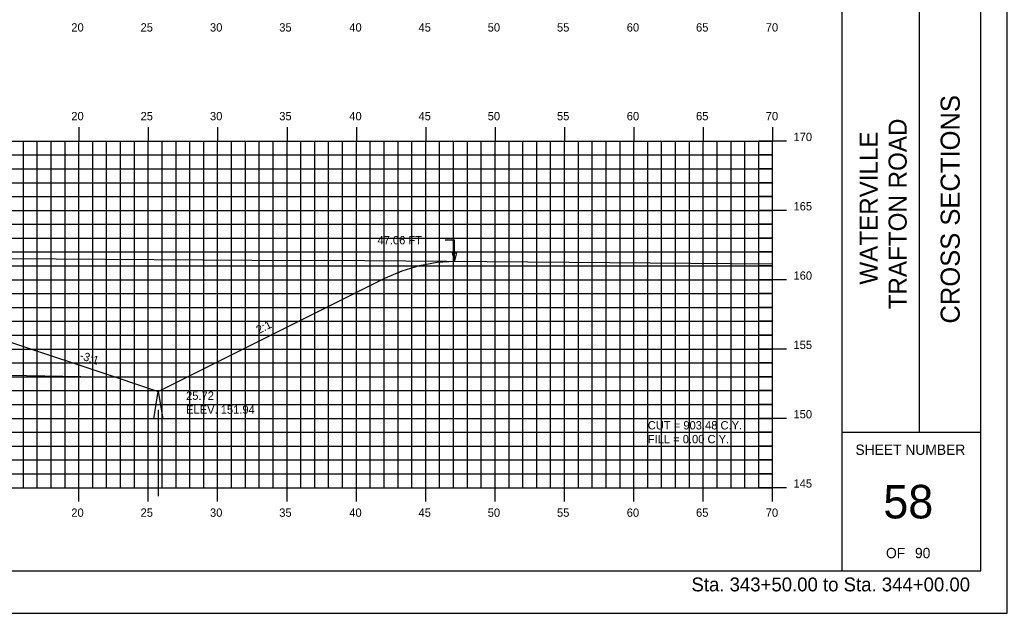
# Model space of a CAD drawing. Extents: x 1143420 to 1143590, y 608981 to 609091.
# Drawn here: x 1143518.8 to 1143590, y 608981.3 to 609024.1 of the extents above; entities that cross this region are included whole.
import ezdxf

# ---------------------------------------------------------------- set-up
doc = ezdxf.new("R2010")
doc.units = 0
for name, color, linetype in [('ANNOTATION', 7, 'Continuous'), ('BORDER', 7, 'Continuous'), ('D_Drainage_Ditch_Line', 7, 'Continuous'), ('D_Roadway_SlopeLines', 7, 'Continuous'), ('D_Roadway_SubGrade', 7, 'Continuous'), ('D_Text_Standard', 7, 'Continuous'), ('H_V ANNOTATION', 7, 'Continuous'), ('HIGHWAY_TITLE', 7, 'Continuous'), ('MAJOR', 7, 'Continuous'), ('MINOR', 7, 'Continuous'), ('PLOT BOUNDARY', 7, 'Continuous'), ('S_Roadway_Centerline', 7, 'Continuous')]:
    doc.layers.add(name, color=color, linetype=linetype)

msp = doc.modelspace()

# ---------------------------------------------------------------- linework, layer by layer
msp.add_lwpolyline([(1143457.318, 609006.487), (1143458.568, 609006.213), (1143459.818, 609005.839), (1143461.068, 609005.365), (1143462.318, 609004.79), (1143477.355, 608997.271), (1143480.355, 608998.271), (1143488.079, 609000.846), (1143488.08, 609000.846), (1143492.08, 609001.006), (1143503.08, 609001.226), (1143514.08, 609001.006), (1143518.08, 609000.846), (1143525.803, 608998.271), (1143528.803, 608997.271), (1143545.139, 609005.439), (1143546.389, 609005.985), (1143547.639, 609006.372), (1143548.889, 609006.599), (1143550.139, 609006.669)])
at = {"layer": 'BORDER'}
for p, q in [((1143578.08, 608984.335), (1143578.08, 609089.335)), ((1143583.671, 608994.338), (1143583.671, 609029.338)), ((1143578.08, 608994.338), (1143588.08, 608994.338))]:
    msp.add_line(p, q, dxfattribs=at)
msp.add_lwpolyline([(1143428.08, 608984.335), (1143588.08, 608984.335), (1143588.08, 609089.335), (1143428.08, 609089.335)], close=True, dxfattribs=at)
at = {"layer": 'D_Drainage_Ditch_Line'}
msp.add_line((1143528.803, 608995.959), (1143528.803, 608989.716), dxfattribs=at)
msp.add_lwpolyline([(1143529.131, 608995.303), (1143528.475, 608995.303), (1143528.803, 608997.271)], close=True, dxfattribs=at)
at = {"layer": 'D_Roadway_SlopeLines'}
for points in [[(1143528.803, 608997.271), (1143545.139, 609005.439), (1143546.389, 609005.985), (1143547.639, 609006.372), (1143548.889, 609006.599), (1143550.139, 609006.669)], [(1143525.803, 608998.271), (1143528.803, 608997.271)]]:
    msp.add_lwpolyline(points, dxfattribs=at)
at = {"layer": 'D_Roadway_SubGrade'}
msp.add_lwpolyline([(1143514.08, 609000.589), (1143514.08, 609000.756), (1143518.08, 609000.596), (1143518.08, 609000.846), (1143518.08, 609000.846), (1143525.803, 608998.271), (1143514.08, 608998.506)], close=True, dxfattribs=at)
at = {"layer": 'D_Text_Standard'}
msp.add_lwpolyline([(1143550.139, 609006.689), (1143550.146, 609008.19), (1143549.466, 609008.19)], dxfattribs=at)
msp.add_lwpolyline([(1143550.139, 609006.689), (1143549.996, 609007.272), (1143550.287, 609007.271)], close=True, dxfattribs=at)
at = {"layer": 'MAJOR'}
for p, q in [((1143523.08, 609016.337), (1143523.08, 609015.335)), ((1143528.08, 609016.337), (1143528.08, 609015.335)), ((1143533.08, 609016.337), (1143533.08, 609015.335)), ((1143538.08, 609016.337), (1143538.08, 609015.335)), ((1143543.08, 609016.337), (1143543.08, 609015.335)), ((1143548.08, 609016.337), (1143548.08, 609015.335)), ((1143553.08, 609016.337), (1143553.08, 609015.335)), ((1143558.08, 609016.337), (1143558.08, 609015.335)), ((1143563.08, 609016.337), (1143563.08, 609015.335)), ((1143568.08, 609016.337), (1143568.08, 609015.335)), ((1143573.08, 609016.337), (1143573.08, 609015.335)), ((1143433.08, 609015.335), (1143573.08, 609015.335)), ((1143433.08, 609015.335), (1143573.08, 609015.335)), ((1143523.08, 608990.335), (1143523.08, 609015.335)), ((1143528.08, 608990.335), (1143528.08, 609015.335)), ((1143533.08, 608990.335), (1143533.08, 609015.335)), ((1143538.08, 608990.335), (1143538.08, 609015.335)), ((1143543.08, 608990.335), (1143543.08, 609015.335)), ((1143548.08, 608990.335), (1143548.08, 609015.335)), ((1143553.08, 608990.335), (1143553.08, 609015.335)), ((1143558.08, 608990.335), (1143558.08, 609015.335)), ((1143563.08, 608990.335), (1143563.08, 609015.335)), ((1143568.08, 608990.335), (1143568.08, 609015.335)), ((1143574.082, 609015.335), (1143572.078, 609015.335)), ((1143573.08, 608990.335), (1143573.08, 609015.335)), ((1143573.08, 608990.335), (1143573.08, 609015.335)), ((1143433.08, 609010.335), (1143573.08, 609010.335)), ((1143574.082, 609010.335), (1143572.078, 609010.335)), ((1143433.08, 609005.335), (1143573.08, 609005.335)), ((1143574.082, 609005.335), (1143572.078, 609005.335)), ((1143433.08, 609000.335), (1143573.08, 609000.335)), ((1143574.082, 609000.335), (1143572.078, 609000.335)), ((1143433.08, 608995.335), (1143573.08, 608995.335)), ((1143574.082, 608995.335), (1143572.078, 608995.335)), ((1143433.08, 608990.335), (1143573.08, 608990.335)), ((1143433.08, 608990.335), (1143573.08, 608990.335)), ((1143523.08, 608989.333), (1143523.08, 608990.335)), ((1143528.08, 608989.333), (1143528.08, 608990.335)), ((1143533.08, 608989.333), (1143533.08, 608990.335)), ((1143538.08, 608989.333), (1143538.08, 608990.335)), ((1143543.08, 608989.333), (1143543.08, 608990.335)), ((1143548.08, 608989.333), (1143548.08, 608990.335)), ((1143553.08, 608989.333), (1143553.08, 608990.335)), ((1143558.08, 608989.333), (1143558.08, 608990.335)), ((1143563.08, 608989.333), (1143563.08, 608990.335)), ((1143568.08, 608989.333), (1143568.08, 608990.335)), ((1143574.082, 608990.335), (1143572.078, 608990.335)), ((1143573.08, 608989.333), (1143573.08, 608990.335))]:
    msp.add_line(p, q, dxfattribs=at)
at = {"layer": 'MINOR'}
for p, q in [((1143519.08, 608990.335), (1143519.08, 609015.335)), ((1143520.08, 608990.335), (1143520.08, 609015.335)), ((1143521.08, 608990.335), (1143521.08, 609015.335)), ((1143522.08, 608990.335), (1143522.08, 609015.335)), ((1143524.08, 608990.335), (1143524.08, 609015.335)), ((1143525.08, 608990.335), (1143525.08, 609015.335)), ((1143526.08, 608990.335), (1143526.08, 609015.335)), ((1143527.08, 608990.335), (1143527.08, 609015.335)), ((1143529.08, 608990.335), (1143529.08, 609015.335)), ((1143530.08, 608990.335), (1143530.08, 609015.335)), ((1143531.08, 608990.335), (1143531.08, 609015.335)), ((1143532.08, 608990.335), (1143532.08, 609015.335)), ((1143534.08, 608990.335), (1143534.08, 609015.335)), ((1143535.08, 608990.335), (1143535.08, 609015.335)), ((1143536.08, 608990.335), (1143536.08, 609015.335)), ((1143537.08, 608990.335), (1143537.08, 609015.335)), ((1143539.08, 608990.335), (1143539.08, 609015.335)), ((1143540.08, 608990.335), (1143540.08, 609015.335)), ((1143541.08, 608990.335), (1143541.08, 609015.335)), ((1143542.08, 608990.335), (1143542.08, 609015.335)), ((1143544.08, 608990.335), (1143544.08, 609015.335)), ((1143545.08, 608990.335), (1143545.08, 609015.335)), ((1143546.08, 608990.335), (1143546.08, 609015.335)), ((1143547.08, 608990.335), (1143547.08, 609015.335)), ((1143549.08, 608990.335), (1143549.08, 609015.335)), ((1143550.08, 608990.335), (1143550.08, 609015.335)), ((1143551.08, 608990.335), (1143551.08, 609015.335)), ((1143552.08, 608990.335), (1143552.08, 609015.335)), ((1143554.08, 608990.335), (1143554.08, 609015.335)), ((1143555.08, 608990.335), (1143555.08, 609015.335)), ((1143556.08, 608990.335), (1143556.08, 609015.335)), ((1143557.08, 608990.335), (1143557.08, 609015.335)), ((1143559.08, 608990.335), (1143559.08, 609015.335)), ((1143560.08, 608990.335), (1143560.08, 609015.335)), ((1143561.08, 608990.335), (1143561.08, 609015.335)), ((1143562.08, 608990.335), (1143562.08, 609015.335)), ((1143564.08, 608990.335), (1143564.08, 609015.335)), ((1143565.08, 608990.335), (1143565.08, 609015.335)), ((1143566.08, 608990.335), (1143566.08, 609015.335)), ((1143567.08, 608990.335), (1143567.08, 609015.335)), ((1143569.08, 608990.335), (1143569.08, 609015.335)), ((1143570.08, 608990.335), (1143570.08, 609015.335)), ((1143571.08, 608990.335), (1143571.08, 609015.335)), ((1143572.08, 608990.335), (1143572.08, 609015.335)), ((1143433.08, 609014.335), (1143573.08, 609014.335)), ((1143573.08, 609014.335), (1143572.078, 609014.335)), ((1143433.08, 609013.335), (1143573.08, 609013.335)), ((1143573.08, 609013.335), (1143572.078, 609013.335)), ((1143433.08, 609012.335), (1143573.08, 609012.335)), ((1143573.08, 609012.335), (1143572.078, 609012.335)), ((1143433.08, 609011.335), (1143573.08, 609011.335)), ((1143573.08, 609011.335), (1143572.078, 609011.335)), ((1143433.08, 609009.335), (1143573.08, 609009.335)), ((1143573.08, 609009.335), (1143572.078, 609009.335)), ((1143433.08, 609008.335), (1143573.08, 609008.335)), ((1143573.08, 609008.335), (1143572.078, 609008.335)), ((1143433.08, 609007.335), (1143573.08, 609007.335)), ((1143573.08, 609007.335), (1143572.078, 609007.335)), ((1143433.08, 609006.335), (1143573.08, 609006.335)), ((1143573.08, 609006.335), (1143572.078, 609006.335)), ((1143433.08, 609004.335), (1143573.08, 609004.335)), ((1143573.08, 609004.335), (1143572.078, 609004.335)), ((1143433.08, 609003.335), (1143573.08, 609003.335)), ((1143573.08, 609003.335), (1143572.078, 609003.335)), ((1143433.08, 609002.335), (1143573.08, 609002.335)), ((1143573.08, 609002.335), (1143572.078, 609002.335)), ((1143433.08, 609001.335), (1143573.08, 609001.335)), ((1143573.08, 609001.335), (1143572.078, 609001.335)), ((1143433.08, 608999.335), (1143573.08, 608999.335)), ((1143573.08, 608999.335), (1143572.078, 608999.335)), ((1143433.08, 608998.335), (1143573.08, 608998.335)), ((1143573.08, 608998.335), (1143572.078, 608998.335)), ((1143433.08, 608997.335), (1143573.08, 608997.335)), ((1143573.08, 608997.335), (1143572.078, 608997.335)), ((1143433.08, 608996.335), (1143573.08, 608996.335)), ((1143573.08, 608996.335), (1143572.078, 608996.335)), ((1143433.08, 608994.335), (1143573.08, 608994.335)), ((1143573.08, 608994.335), (1143572.078, 608994.335)), ((1143433.08, 608993.335), (1143573.08, 608993.335)), ((1143573.08, 608993.335), (1143572.078, 608993.335)), ((1143433.08, 608992.335), (1143573.08, 608992.335)), ((1143573.08, 608992.335), (1143572.078, 608992.335)), ((1143433.08, 608991.335), (1143573.08, 608991.335)), ((1143573.08, 608991.335), (1143572.078, 608991.335))]:
    msp.add_line(p, q, dxfattribs=at)
at = {"layer": 'PLOT BOUNDARY'}
msp.add_lwpolyline([(1143419.986, 608981.276), (1143589.986, 608981.276), (1143589.986, 609091.276), (1143419.986, 609091.276)], close=True, dxfattribs=at)
at = {"layer": 'S_Roadway_Centerline'}
msp.add_lwpolyline([(1143433.08, 609006.398), (1143437.983, 609006.589), (1143446.959, 609006.499), (1143458.437, 609006.485), (1143462.967, 609005.025), (1143468.267, 609004.229), (1143470.266, 609004.634), (1143472.319, 609005.24), (1143474.432, 609005.454), (1143474.512, 609005.456), (1143482.15, 609005.563), (1143485.877, 609005.61), (1143488.245, 609005.61), (1143496.712, 609005.592), (1143496.838, 609005.583), (1143501.911, 609005.274), (1143502.012, 609005.24), (1143504.24, 609004.385), (1143504.505, 609004.496), (1143512.688, 609007.008), (1143517.913, 609006.865), (1143539.07, 609006.733), (1143540.761, 609006.746), (1143573.08, 609006.481)], dxfattribs=at)

# ---------------------------------------------------------------- texts
at = {"layer": 'ANNOTATION'}
for s, rotation, p in [('2:1', 26.56505, (1143536.043, 609001.41)), ('-3:1', 341.56521, (1143523.091, 608999.63))]:
    msp.add_text(s, height=0.6, rotation=rotation, dxfattribs=at).set_placement(p)
at = {"layer": 'BORDER'}
msp.add_text('CROSS SECTIONS', height=1.37787, rotation=90, dxfattribs=at).set_placement((1143586.564, 609002.172))
for s, height, p in [('SHEET NUMBER', 0.74527, (1143579.045, 608992.701)), ('58', 2.4194, (1143581.055, 608988.118)), ('OF', 0.7453, (1143581.247, 608985.248)), ('90', 0.7453, (1143583.336, 608985.248))]:
    msp.add_text(s, height=height, dxfattribs=at).set_placement(p)
at = {"layer": 'D_Text_Standard'}
for s, p in [('47.06 FT', (1143544.6, 609007.89)), ('25.72', (1143530.803, 608996.671)), ('ELEV. 151.94', (1143530.803, 608995.669)), ('CUT = 903.48 C.Y.', (1143564.08, 608994.535)), ('FILL = 0.00 C.Y.', (1143564.08, 608993.539))]:
    msp.add_text(s, height=0.6, dxfattribs=at).set_placement(p)
at = {"layer": 'H_V ANNOTATION'}
for s, height, p in [('20', 0.6, (1143522.534, 609023.235)), ('25', 0.6, (1143527.526, 609023.235)), ('30', 0.6, (1143532.528, 609023.235)), ('35', 0.6, (1143537.52, 609023.235)), ('40', 0.6, (1143542.566, 609023.235)), ('45', 0.6, (1143547.558, 609023.235)), ('50', 0.6, (1143552.544, 609023.235)), ('55', 0.6, (1143557.536, 609023.235)), ('60', 0.6, (1143562.566, 609023.235)), ('65', 0.6, (1143567.558, 609023.235)), ('70', 0.6, (1143572.582, 609023.235)), ('20', 0.6, (1143522.534, 609016.835)), ('25', 0.6, (1143527.526, 609016.835)), ('30', 0.6, (1143532.528, 609016.835)), ('35', 0.6, (1143537.52, 609016.835)), ('40', 0.6, (1143542.566, 609016.835)), ('45', 0.6, (1143547.558, 609016.835)), ('50', 0.6, (1143552.544, 609016.835)), ('55', 0.6, (1143557.536, 609016.835)), ('60', 0.6, (1143562.566, 609016.835)), ('65', 0.6, (1143567.558, 609016.835)), ('70', 0.6, (1143572.582, 609016.835)), ('170', 0.6, (1143574.58, 609015.335)), ('165', 0.6, (1143574.58, 609010.335)), ('160', 0.6, (1143574.58, 609005.335)), ('155', 0.6, (1143574.58, 609000.335)), ('150', 0.6, (1143574.58, 608995.335)), ('145', 0.6, (1143574.58, 608990.335)), ('20', 0.6, (1143522.534, 608988.235)), ('25', 0.6, (1143527.526, 608988.235)), ('30', 0.6, (1143532.528, 608988.235)), ('35', 0.6, (1143537.52, 608988.235)), ('40', 0.6, (1143542.566, 608988.235)), ('45', 0.6, (1143547.558, 608988.235)), ('50', 0.6, (1143552.544, 608988.235)), ('55', 0.6, (1143557.536, 608988.235)), ('60', 0.6, (1143562.566, 608988.235)), ('65', 0.6, (1143567.558, 608988.235)), ('70', 0.6, (1143572.582, 608988.235)), ('Sta. 343+50.00 to Sta. 344+00.00', 1.0002, (1143567.226, 608982.855))]:
    msp.add_text(s, height=height, dxfattribs=at).set_placement(p)
at = {"layer": 'HIGHWAY_TITLE'}
for s, height, p in [('TRAFTON ROAD', 1.30428, (1143582.739, 609003.201)), ('WATERVILLE', 1.3043, (1143580.652, 609004.98))]:
    msp.add_text(s, height=height, rotation=90, dxfattribs=at).set_placement(p)

doc.saveas('drawing.dxf')
